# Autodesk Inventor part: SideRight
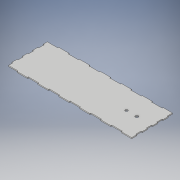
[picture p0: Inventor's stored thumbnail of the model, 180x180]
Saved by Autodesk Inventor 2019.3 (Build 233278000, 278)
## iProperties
Created: 2020-02
Part Number: SideRight
Material: Generic
Document SubType Name: Modeling
Designer: KrystynWikoff
Density: 1 g/cm^3
Appearance: Default
Author: KrystynWikoff
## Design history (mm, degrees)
sketch "Sketch1"
  geometry: L1 (0, 0)-(304.8, 0); L2 (304.8, 0)-(304.8, -101.6); L3 (304.8, -101.6)-(0, -101.6); L4 (0, -101.6)-(0, 0)
  constraints: 8 end point, 2 parallel, 1 horizontal, 1 perpendicular
  dimensions: "d0" = 101.6 distance of L3.end L1.start; "d1" = 304.8 distance of L1.start L1.end
extrude "Extrusion1" new body sketch "Sketch1" distance "d2" = 2.3622; taper "d3" = 0 deg
sketch "Sketch2"
  geometry: L1 (0, 0)-(0, 101.6) reference; L2 (-304.8, 0)-(0, 0) reference; C1 r 3.683 at (-38.1, 50.8); C2 r 3.175 at (-63.5, 50.8)
  constraints: 2 centre point
  dimensions: "d4" = 7.366 diameter of C1; "d5" = 38.1 distance from line of L1 C1.centre; "d6" = 50.8 distance from line of L2 C1.centre; "d7" = 6.35 diameter of C2; "d8" = 25.4 distance of C1.centre C2.centre; "d9" = 50.8 distance from line of L2 C2.centre
extrude "Extrusion2" cut sketch "Sketch2" distance "d10" = 2.3622; taper "d11" = 0 deg
sketch "Sketch3" dims "d20" = 25.4, "d30" = 25.4, "d39" = 25.4
  geometry: L1 (0, 101.6)-(0, 0) reference; L2 (0, 12.7)-(-2.362, 12.7); L3 (-2.362, 12.7)-(-2.362, 25.4); L4 (-2.362, 25.4)-(0, 25.4); L5 (0, 25.4)-(0, 12.7); L6 (-304.8, 0)-(0, 0) reference; L7 (0, 38.1)-(-2.362, 38.1); L8 (-2.362, 38.1)-(-2.362, 50.8); L9 (-2.362, 50.8)-(0, 50.8); L10 (0, 50.8)-(0, 38.1); L11 (0, 63.5)-(-2.362, 63.5); L12 (-2.362, 63.5)-(-2.362, 76.2); L13 (-2.362, 76.2)-(0, 76.2); L14 (0, 76.2)-(0, 63.5); L15 (0, 88.9)-(-2.362, 88.9); L16 (-2.362, 88.9)-(-2.362, 101.6); L17 (-2.362, 101.6)-(0, 101.6); L18 (0, 101.6)-(0, 88.9); L19 (0, 0)-(-304.8, 0) reference; L20 (-25.4, 0)-(-50.8, 0); L21 (-50.8, 0)-(-50.8, 2.362); L22 (-50.8, 2.362)-(-25.4, 2.362); L23 (-25.4, 2.362)-(-25.4, 0); L24 (-76.2, 2.362)-(-76.2, 0); L25 (-76.2, 0)-(-101.6, 0); L26 (-101.6, 0)-(-101.6, 2.362); L27 (-101.6, 2.362)-(-76.2, 2.362); L28 (-127, 2.362)-(-127, 0); L29 (-127, 0)-(-152.4, 0); L30 (-152.4, 0)-(-152.4, 2.362); L31 (-152.4, 2.362)-(-127, 2.362); L32 (-177.8, 2.362)-(-177.8, 0); L33 (-177.8, 0)-(-203.2, 0); L34 (-203.2, 0)-(-203.2, 2.362); L35 (-203.2, 2.362)-(-177.8, 2.362); L36 (-228.6, 2.362)-(-228.6, 0); L37 (-228.6, 0)-(-254, 0); L38 (-254, 0)-(-254, 2.362); L39 (-254, 2.362)-(-228.6, 2.362); L40 (-279.4, 2.362)-(-279.4, 0); L41 (-279.4, 0)-(-304.8, 0); L42 (-304.8, 0)-(-304.8, 2.362); L43 (-304.8, 2.362)-(-279.4, 2.362); L44 (-304.8, 0)-(-304.8, 101.6) reference; L45 (-304.8, 0)-(-302.438, 0); L46 (-302.438, 0)-(-302.438, 12.7); L47 (-302.438, 12.7)-(-304.8, 12.7); L48 (-304.8, 12.7)-(-304.8, 0); L49 (-302.438, 25.4)-(-302.438, 38.1); L50 (-304.8, 25.4)-(-304.8, 27.762); L51 (-302.438, 38.1)-(-304.8, 38.1); L52 (-304.8, 38.1)-(-304.8, 25.4); L53 (-304.8, 25.4)-(-302.438, 25.4); L54 (-302.438, 50.8)-(-302.438, 63.5); L55 (-304.8, 50.8)-(-304.8, 53.162); L56 (-302.438, 63.5)-(-304.8, 63.5); L57 (-304.8, 63.5)-(-304.8, 50.8); L58 (-304.8, 50.8)-(-302.438, 50.8); L59 (-302.438, 76.2)-(-302.438, 88.9); L60 (-304.8, 76.2)-(-304.8, 78.562); L61 (-302.438, 88.9)-(-304.8, 88.9); L62 (-304.8, 88.9)-(-304.8, 76.2); L63 (-304.8, 76.2)-(-302.438, 76.2); L64 (-302.438, 101.6)-(-302.438, 114.3)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
  constraints: 128 end point, 6 parallel, 4 horizontal, 3 perpendicular, 2 point on line, 2 vertical, 1 collinear, 107 other
  dimensions: "d12" = 2.3622 distance of L2.start L2.end; "d13" = 12.7 distance of L2.end L3.end; "d14" = 12.7 distance between parallel lines of L6 L2; "d17" = 25.4 distance of L2.start L7.start; "d22" = 25.4 distance between parallel lines of L1 L23; "d23" = 25.4 distance of L21.end L22.end; "d24" = 2.3622 distance of L22.end L20.start; "d27" = 50.8 distance of L22.end L24.start; "d32" = 12.7 distance of L45.end L46.end; "d33" = 2.3622 distance of L46.end L47.end; "d36" = 25.4 distance of L46.end L49.end
extrude "Extrusion3" cut sketch "Sketch3" distance "d41" = 2.3622; taper "d42" = 0 deg
sketch "Sketch4" dims "d50" = 25.4
  geometry: L1 (-304.8, 101.6)-(-304.8, 88.9) reference; L2 (-304.8, 101.6)-(-279.4, 101.6); L3 (-279.4, 101.6)-(-279.4, 99.238); L4 (-279.4, 99.238)-(-304.8, 99.238); L5 (-304.8, 99.238)-(-304.8, 101.6); L6 (-254, 101.6)-(-228.6, 101.6); L7 (-228.6, 101.6)-(-228.6, 99.238); L8 (-228.6, 99.238)-(-254, 99.238); L9 (-254, 99.238)-(-254, 101.6); L10 (-203.2, 101.6)-(-177.8, 101.6); L11 (-177.8, 101.6)-(-177.8, 99.238); L12 (-177.8, 99.238)-(-203.2, 99.238); L13 (-203.2, 99.238)-(-203.2, 101.6); L14 (-152.4, 101.6)-(-127, 101.6); L15 (-127, 101.6)-(-127, 99.238); L16 (-127, 99.238)-(-152.4, 99.238); L17 (-152.4, 99.238)-(-152.4, 101.6); L18 (-101.6, 101.6)-(-76.2, 101.6); L19 (-76.2, 101.6)-(-76.2, 99.238); L20 (-76.2, 99.238)-(-101.6, 99.238); L21 (-101.6, 99.238)-(-101.6, 101.6); L22 (-50.8, 101.6)-(-25.4, 101.6); L23 (-25.4, 101.6)-(-25.4, 99.238); L24 (-25.4, 99.238)-(-50.8, 99.238); L25 (-50.8, 99.238)-(-50.8, 101.6); 1 further point
  constraints: 48 end point, 2 horizontal, 2 parallel, 1 collinear, 1 perpendicular, 39 other
  dimensions: "d43" = 25.4 distance of L3.end L4.end; "d44" = 2.3622 distance of L2.end L3.end; "d47" = 50.8 distance of L3.end L7.end
extrude "Extrusion4" cut sketch "Sketch4" extent not by distance; stored distance "d52" = 50.8 (= d47); taper "d53" = 0 deg
body "Solid1"
